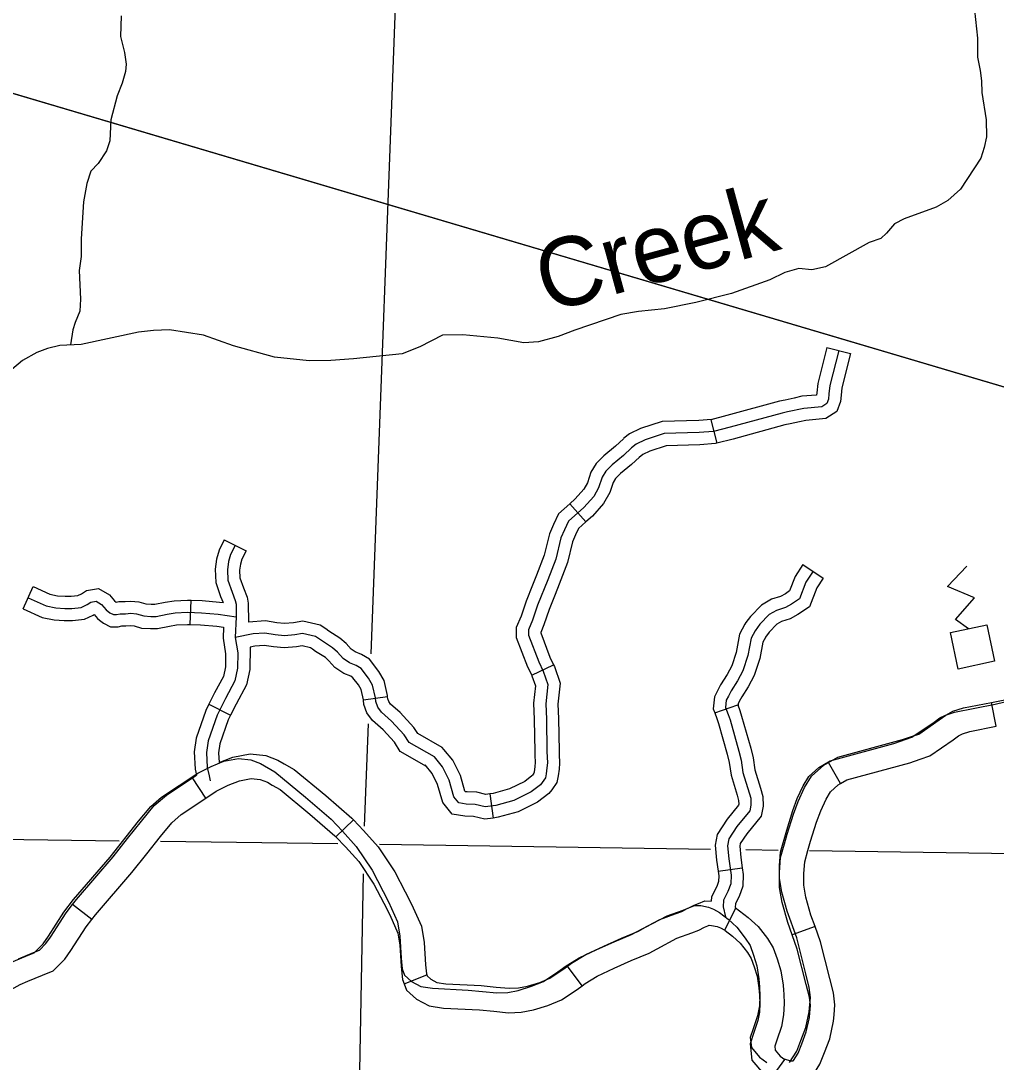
# Model space of a CAD drawing. Extents: x 0 to 3171, y 0 to 2059.
# Drawn here: x 1109.9 to 1210, y 749 to 855.9 of the extents above; entities that cross this region are included whole.
import ezdxf

# ---------------------------------------------------------------- set-up
doc = ezdxf.new("R2010")
doc.units = 0
for name, color, linetype in [('Default', 7, 'Continuous'), ('Level 35', 7, 'Continuous'), ('Level 45', 7, 'Continuous'), ('Level 5', 7, 'Continuous'), ('Level 57', 7, 'Continuous')]:
    doc.layers.add(name, color=color, linetype=linetype)

msp = doc.modelspace()

# ---------------------------------------------------------------- linework, layer by layer
at = {"layer": 'Default'}
for points in [[(641.57, 882.9), (992.89, 882.9), (1640.89, 690.88)], [(1029.42, 872.07), (1640.89, 690.88)]]:
    msp.add_lwpolyline(points, dxfattribs=at)
at = {"layer": 'Level 35'}
for points in [[(1207.74, 856.98), (1208.06, 854.1), (1208.04, 852.17), (1208.33, 850.79), (1208.46, 849.74), (1208.48, 848.52), (1208.95, 845.71), (1208.96, 843.97), (1208.74, 842.87), (1208.38, 841.78), (1206.31, 838.6), (1205, 837.44), (1203.81, 836.75), (1200.53, 835.58), (1199.52, 835.04), (1198.73, 834.1), (1198.14, 833.53), (1196.95, 833.15), (1192.45, 830.64), (1191.07, 830.33), (1189.72, 830.47), (1188.3, 830.07), (1186.73, 829.31), (1182.8, 827.9), (1179.15, 826.97), (1175.92, 826.32), (1173.28, 826.05), (1171.47, 825.75), (1166.72, 824.14), (1165.03, 823.47), (1163.01, 822.93), (1161.5, 822.83), (1158.85, 823.3), (1155.23, 823.67), (1153.17, 823.61), (1150.82, 822.44), (1149.02, 821.71), (1144.04, 821.18), (1141.7, 821.01), (1139.47, 820.98), (1135.93, 821.37), (1131.71, 822.52), (1128.63, 823.62), (1125.14, 824.16), (1123.49, 824.11), (1121.97, 823.92), (1116.08, 822.68), (1113.91, 822.56), (1112.63, 822.27), (1111.55, 821.85), (1110.05, 821.03), (1107.65, 819.02)], [(1120.17, 856.41), (1120.13, 854.26), (1120.53, 852.65), (1120.7, 851.43), (1120.62, 850.67), (1120.3, 849.48), (1119.79, 848.19), (1119.11, 845.74), (1119.03, 843.57), (1118.69, 842.55), (1117.82, 841.23), (1117.09, 840.44), (1116.65, 839.2), (1116.31, 837.32), (1116.07, 833.51), (1116.07, 831.71), (1115.86, 830.26), (1116.03, 827.33), (1115.94, 826.09), (1115.45, 824.91), (1115.24, 824.17), (1114.98, 822.62)]]:
    msp.add_lwpolyline(points, dxfattribs=at)
at = {"layer": 'Level 45'}
for p, q in [((1192.6, 822.36), (1195.03, 821.75)), ((1180.69, 814.95), (1181.32, 812.53)), ((1166.22, 806.32), (1167.88, 804.45)), ((1130.76, 802.61), (1133, 801.5)), ((1190.14, 800.08), (1192.23, 798.7)), ((1110.14, 795.54), (1111.17, 797.82)), ((1127.28, 793.92), (1127.38, 796.42)), ((1162.31, 788.72), (1164.56, 789.8)), ((1129.18, 785.74), (1131.42, 784.62)), ((1147.52, 786.49), (1145.04, 786.17)), ((1181.09, 784.85), (1183.45, 785.68)), ((1209.97, 783.48), (1209.48, 785.93)), ((1194.01, 777.61), (1192.78, 779.78)), ((1128.88, 776.11), (1127.49, 778.19)), ((1158.02, 776.55), (1158.35, 774.07)), ((1142.22, 772.14), (1144.02, 773.87)), ((1181.44, 768.61), (1183.91, 768.96)), ((1117.18, 763.67), (1115.2, 765.2)), ((1182.12, 762.56), (1183.26, 764.84)), ((1191.38, 762.92), (1189.03, 762.08)), ((1167.48, 756.86), (1165.98, 758.86)), ((1149.22, 757.05), (1151.54, 757.97)), ((1186.82, 747.27), (1188.28, 749.3))]:
    msp.add_line(p, q, dxfattribs=at)
for points in [[(1193.81, 822.06), (1192.9, 818.45), (1192.81, 817.59), (1192.76, 817.07), (1192.6, 816.6), (1192.08, 816.28), (1190.24, 816.11), (1188.57, 815.74), (1188, 815.63), (1182.66, 814.17), (1180.96, 813.73), (1179.51, 813.62), (1175.89, 813.53), (1173.94, 812.89), (1173.03, 812.44), (1172.55, 812.06), (1171.73, 811.28), (1170.56, 810.33), (1169.93, 809.68), (1169.53, 809.04), (1169.18, 807.97), (1168.67, 807.08), (1167.66, 805.93), (1166.1, 804.54), (1165.69, 803.66), (1165.31, 802.83), (1164.79, 800.65), (1163.97, 798.52), (1162.92, 795.9), (1162.4, 794.36), (1161.98, 793.37), (1161.98, 792.84), (1163.03, 790.1), (1163.49, 789.15), (1163.96, 787.76), (1163.75, 785.8), (1163.82, 784.23), (1163.87, 780.91), (1163.92, 779.74), (1163.87, 779.22), (1163.78, 778.59), (1163.71, 778.19), (1163.38, 777.7), (1163.2, 777.48), (1162.26, 776.76), (1160.48, 775.87), (1158.62, 775.37), (1157.55, 775.22), (1156.51, 775.47), (1155.58, 775.49), (1154.83, 775.62), (1154.33, 776.25), (1153.83, 777.97), (1153.16, 779.31), (1152.32, 780.34), (1149.72, 781.82), (1149.24, 782.6), (1147.93, 784.01), (1146.89, 784.92), (1146.53, 785.43), (1146.32, 786.01), (1146.27, 786.42)], [(1192.6, 822.36), (1191.67, 818.68), (1191.56, 817.71), (1191.54, 817.48), (1190.04, 817.35), (1189.25, 817.17)], [(1195.03, 821.75), (1194.14, 818.23), (1194.05, 817.46), (1193.99, 816.81), (1193.63, 815.78), (1192.5, 815.06), (1190.43, 814.88), (1189.8, 814.73)], [(1189.25, 817.17), (1188.32, 816.96), (1187.72, 816.85), (1182.34, 815.38), (1180.69, 814.95)], [(1180.75, 814.96), (1179.45, 814.87), (1175.68, 814.77), (1173.47, 814.05), (1172.36, 813.5), (1171.78, 813.04)], [(1189.8, 814.73), (1188.83, 814.51), (1188.28, 814.41), (1182.99, 812.96), (1181.32, 812.53)], [(1171.78, 813.04), (1171.73, 813), (1170.9, 812.22), (1169.72, 811.25), (1168.94, 810.45), (1168.39, 809.58), (1168.04, 808.48), (1167.65, 807.81), (1166.78, 806.81), (1166.22, 806.32)], [(1181.32, 812.53), (1181.16, 812.49), (1179.57, 812.37), (1176.11, 812.28), (1174.42, 811.73), (1173.71, 811.38), (1173.33, 811.08)], [(1173.37, 811.11), (1172.55, 810.34), (1171.41, 809.41), (1170.92, 808.9), (1170.68, 808.51), (1170.33, 807.46), (1169.69, 806.35), (1168.55, 805.05), (1167.88, 804.45)], [(1166.22, 806.32), (1165.07, 805.3), (1164.55, 804.18), (1164.13, 803.24), (1163.59, 801.03), (1162.8, 798.98), (1162.39, 797.95)], [(1167.88, 804.45), (1167.12, 803.78), (1166.82, 803.14), (1166.5, 802.42), (1165.98, 800.28), (1165.13, 798.07), (1164.71, 797.01)], [(1131.88, 802.05), (1131.4, 801.1), (1131.2, 800.39), (1131.08, 799.55), (1131.13, 798.48), (1131.56, 797.24), (1131.9, 796.4), (1131.97, 796.01), (1131.99, 794.71), (1131.9, 792.58), (1132.15, 791.01), (1132.13, 789.46), (1131.86, 788.16), (1130.88, 786.34), (1130.02, 784.62), (1129.1, 781.99), (1128.93, 780.81), (1129.01, 779.26), (1129.23, 778.39), (1129.33, 777.9)], [(1130.76, 802.61), (1130.23, 801.55), (1129.97, 800.65), (1129.83, 799.61), (1129.89, 798.24), (1130.39, 796.8), (1130.64, 796.18)], [(1133, 801.5), (1132.57, 800.64), (1132.42, 800.13), (1132.34, 799.49), (1132.37, 798.72), (1132.73, 797.68), (1133.11, 796.74), (1133.22, 796.13), (1133.25, 794.18)], [(1190.14, 800.08), (1189.33, 798.85), (1188.75, 797.37), (1188.34, 797.09), (1187.84, 796.82), (1186.92, 796.53), (1185.88, 795.93), (1184.77, 794.76), (1184.29, 794.12)], [(1191.19, 799.39), (1190.44, 798.27), (1189.78, 796.55), (1188.98, 796.02), (1188.34, 795.67), (1187.43, 795.38), (1186.67, 794.94), (1185.73, 793.95), (1185.23, 793.29), (1184.82, 792.53), (1184.5, 790.74), (1183.99, 789.19), (1183.43, 788.16), (1182.77, 787.13), (1182.49, 786.57), (1182.28, 786.15), (1182.21, 785.42), (1182.47, 784.7), (1182.66, 784.14), (1183.57, 780.93), (1183.8, 779.99), (1183.99, 778.75), (1184.79, 776.09), (1184.81, 775.38), (1184.69, 774.82), (1183.36, 773.21), (1182.52, 771.92), (1182.4, 771.22), (1182.52, 769.87), (1182.76, 768.19), (1182.73, 767.32), (1182.45, 766.53), (1181.99, 765.64), (1181.96, 764.96), (1182.19, 763.93)], [(1192.23, 798.7), (1191.56, 797.69), (1190.8, 795.73), (1189.63, 794.95), (1188.83, 794.51), (1187.93, 794.23), (1187.45, 793.95), (1186.68, 793.14), (1186.29, 792.62)], [(1111.17, 797.82), (1112.87, 797.05), (1113.65, 796.88), (1114.43, 796.83), (1115.05, 796.83), (1115.73, 796.91), (1116.11, 797.09), (1116.63, 797.41), (1117.86, 797.62), (1118.99, 796.96), (1119.5, 796.35), (1119.5, 796.35)], [(1162.39, 797.95), (1161.74, 796.33), (1161.23, 794.8), (1160.73, 793.63), (1160.73, 792.6), (1161.88, 789.6), (1162.31, 788.72)], [(1110.66, 796.68), (1112.48, 795.86), (1113.48, 795.64), (1114.39, 795.58), (1115.12, 795.58), (1116.08, 795.69), (1116.71, 795.99), (1117.08, 796.22), (1117.62, 796.31), (1118.17, 795.99), (1118.63, 795.45), (1119.04, 795.13), (1119.4, 794.95), (1119.72, 794.95), (1120.08, 795.04), (1120.63, 795.04), (1121.18, 795.08), (1121.77, 795.04), (1122.5, 794.81), (1123.22, 794.76), (1123.77, 794.76), (1124.91, 795), (1125.73, 795.13), (1126.99, 795.19), (1128.42, 795.13), (1130.15, 794.99), (1131.99, 794.71)], [(1119.5, 796.35), (1119.67, 796.22), (1119.93, 796.29), (1120.58, 796.29), (1121.17, 796.34), (1122.01, 796.27), (1122.72, 796.05), (1123.26, 796.01), (1123.64, 796.01), (1124.69, 796.23), (1125.61, 796.37), (1126.98, 796.44), (1127.38, 796.42)], [(1127.38, 796.42), (1128.49, 796.38), (1130.29, 796.23), (1130.64, 796.18)], [(1164.71, 797.01), (1164.09, 795.47), (1163.57, 793.91), (1163.23, 793.12), (1163.23, 793.07), (1164.18, 790.59), (1164.56, 789.8)], [(1110.14, 795.54), (1112.09, 794.66), (1113.31, 794.4), (1114.35, 794.33), (1115.19, 794.33), (1116.42, 794.47), (1117.32, 794.9), (1117.41, 794.96), (1117.75, 794.54), (1117.97, 794.38)], [(1117.97, 794.38), (1118.37, 794.07), (1119.1, 793.7), (1119.87, 793.7), (1120.24, 793.79), (1120.68, 793.79), (1121.18, 793.83), (1121.53, 793.8), (1122.27, 793.57), (1123.19, 793.51), (1123.9, 793.51), (1125.14, 793.77), (1125.85, 793.88), (1126.99, 793.93), (1127.28, 793.92)], [(1141.2, 793.47), (1140.62, 793.85), (1138.83, 794.28), (1137.86, 794.11), (1136.93, 794.03), (1136.16, 794.11), (1134.98, 794.31), (1133.25, 794.18)], [(1184.29, 794.12), (1184.17, 793.96), (1183.63, 792.94), (1183.29, 791.05), (1182.84, 789.69), (1182.35, 788.8), (1181.68, 787.75), (1181.37, 787.13), (1181.06, 786.5), (1180.94, 785.27), (1181.09, 784.85)], [(1127.28, 793.92), (1128.34, 793.88), (1130, 793.75), (1130.7, 793.64)], [(1130.7, 793.64), (1130.65, 792.51), (1130.9, 790.92), (1130.88, 789.6), (1130.67, 788.59), (1129.77, 786.91), (1129.18, 785.74)], [(1146.27, 786.42), (1145.99, 787.71), (1145.57, 788.42), (1144.82, 789.42), (1144.3, 789.73), (1143.62, 790), (1142.95, 790.45), (1142.38, 791.1), (1141.88, 791.53), (1140.83, 792.21), (1140.11, 792.69), (1138.79, 793.01), (1138.02, 792.87), (1136.93, 792.78), (1135.99, 792.87), (1134.92, 793.05), (1133.74, 792.96), (1131.9, 792.58)], [(1147.52, 786.49), (1147.5, 786.63), (1147.17, 788.17), (1146.62, 789.12), (1145.67, 790.36), (1144.86, 790.86), (1144.21, 791.11), (1143.79, 791.4), (1143.27, 791.99), (1142.63, 792.54), (1141.51, 793.26), (1141.2, 793.47)], [(1186.29, 792.62), (1186.29, 792.61), (1186.02, 792.11), (1185.72, 790.43), (1185.14, 788.69), (1184.51, 787.53), (1183.86, 786.52), (1183.61, 786.01), (1183.5, 785.8), (1183.48, 785.58), (1183.45, 785.68)], [(1133.41, 791.62), (1133.38, 789.32), (1133.04, 787.73), (1131.99, 785.76), (1131.42, 784.62)], [(1139.81, 791.39), (1139.6, 791.53), (1138.75, 791.73), (1138.18, 791.63), (1136.92, 791.52), (1135.83, 791.63), (1134.86, 791.79), (1133.91, 791.72), (1133.41, 791.62)], [(1145.04, 786.17), (1145.04, 786.21), (1144.81, 787.25), (1144.53, 787.73), (1143.97, 788.47), (1143.75, 788.61), (1143.03, 788.89), (1142.12, 789.51), (1141.5, 790.21), (1141.14, 790.53), (1140.14, 791.17), (1139.81, 791.39)], [(1164.56, 789.8), (1164.65, 789.62), (1165.24, 787.9), (1165, 785.76), (1165.07, 784.27), (1165.12, 780.94), (1165.14, 780.61)], [(1162.31, 788.72), (1162.33, 788.67), (1162.69, 787.62), (1162.49, 785.84), (1162.57, 784.19), (1162.62, 780.87), (1162.64, 780.51)], [(1209.48, 785.93), (1210.85, 786.2), (1212.89, 786.67), (1214.21, 787.13), (1214.95, 787.44), (1217.6, 788.54)], [(1203.59, 783.91), (1204.2, 784.34), (1204.76, 784.64), (1205.69, 784.94), (1209.85, 785.76), (1211.98, 786.25), (1213.41, 786.75)], [(1129.18, 785.74), (1128.86, 785.1), (1127.88, 782.28), (1127.68, 780.87), (1127.77, 779.07), (1127.92, 778.48)], [(1151.5, 779.37), (1148.83, 780.89), (1148.24, 781.84), (1147.06, 783.11), (1145.96, 784.07), (1145.4, 784.85), (1145.1, 785.73), (1145.04, 786.17)], [(1153.31, 781.11), (1153.14, 781.31), (1150.62, 782.75), (1150.23, 783.36), (1148.8, 784.91), (1147.83, 785.76), (1147.65, 786.01), (1147.55, 786.3), (1147.52, 786.49)], [(1183.45, 785.68), (1183.65, 785.11), (1183.85, 784.51), (1184.78, 781.25), (1185.03, 780.24), (1185.21, 779.03), (1185.77, 777.14)], [(1201.37, 782.47), (1202.02, 782.69), (1204.12, 784.15), (1204.79, 784.63), (1205.53, 785.02), (1206.63, 785.37), (1209.48, 785.93)], [(1131.42, 784.62), (1131.17, 784.13), (1130.32, 781.69), (1130.19, 780.75), (1130.24, 779.76)], [(1181.09, 784.85), (1181.29, 784.29), (1181.46, 783.77), (1182.36, 780.61), (1182.58, 779.75), (1182.77, 778.48), (1183.38, 776.43)], [(1188.77, 748.98), (1189.52, 750.15), (1189.94, 751.22), (1190.43, 752.56), (1190.79, 754.18), (1190.9, 755.65), (1190.78, 756.69), (1190.43, 758.07), (1189.5, 761.76), (1188.52, 764.5), (1187.98, 766.45), (1187.74, 767.85), (1187.72, 769.21), (1187.84, 770.57), (1188.48, 772.83), (1189.11, 774.84), (1189.55, 776.07), (1190.15, 777.38), (1190.75, 778.34), (1191.77, 779.27), (1192.93, 779.93), (1199.48, 781.72), (1201.33, 782.35), (1203.59, 783.91)], [(1202.17, 780.11), (1203.15, 780.44), (1205.56, 782.11), (1206.11, 782.5), (1206.5, 782.7), (1207.26, 782.95), (1209.97, 783.48)], [(1192.78, 779.78), (1193.71, 780.31), (1200.37, 782.13), (1201.37, 782.47)], [(1130.24, 779.76), (1131.63, 780.31), (1133.43, 780.65), (1135.04, 780.47), (1136.26, 780.01), (1136.92, 779.63)], [(1158.02, 776.55), (1157.62, 776.49), (1156.67, 776.71), (1155.7, 776.74), (1155.51, 776.77), (1155.46, 776.84), (1155, 778.42), (1154.22, 779.99), (1153.31, 781.11)], [(1162.64, 780.51), (1162.67, 779.77), (1162.63, 779.37), (1162.55, 778.79), (1162.53, 778.67), (1162.38, 778.45), (1162.33, 778.39), (1161.6, 777.83), (1160.03, 777.05), (1158.37, 776.59), (1158.02, 776.55)], [(1165.14, 780.61), (1165.17, 779.71), (1165.12, 779.07), (1165.01, 778.39), (1164.9, 777.72), (1164.38, 776.95), (1164.06, 776.57), (1162.92, 775.7), (1160.93, 774.7), (1158.86, 774.14), (1158.35, 774.07)], [(1108.03, 758.89), (1110.4, 759.89), (1111.26, 760.23), (1112.17, 761.16), (1112.72, 761.94), (1114.3, 764.39), (1115.31, 765.7), (1119.06, 770.06), (1121.98, 773.73), (1123.22, 775.25), (1124.34, 776.21), (1128.05, 778.68), (1129.42, 779.37), (1130.73, 779.89), (1132.23, 780.17), (1133.49, 780.03), (1134.47, 779.65), (1135.97, 778.81), (1139.11, 776.22), (1141.72, 773.94), (1142.89, 772.73), (1144.3, 771.13), (1145.93, 768.7), (1147.62, 765.47), (1148.55, 763.4), (1148.78, 761.95), (1148.92, 759.7), (1149.02, 758.58), (1149.27, 757.93), (1149.97, 757.29), (1150.93, 756.78), (1152.13, 756.59), (1155.8, 756.4), (1158.72, 756.12), (1159.85, 756.17), (1160.92, 756.38), (1162.3, 756.8), (1163.52, 757.29), (1164.99, 758.28), (1165.83, 758.91), (1167.19, 759.73), (1168.99, 760.57), (1170.77, 761.37), (1172.56, 762.13)], [(1136.92, 779.63), (1137.93, 779.06), (1141.17, 776.39), (1143.84, 774.07), (1144.02, 773.87)], [(1158.35, 774.07), (1157.49, 773.96), (1156.35, 774.22), (1155.45, 774.25), (1154.15, 774.47), (1153.19, 775.67), (1152.66, 777.51), (1152.1, 778.63), (1151.37, 779.53)], [(1188.25, 771.41), (1188.53, 772.41), (1189.17, 774.46), (1189.65, 775.76), (1190.3, 777.19), (1191.03, 778.36), (1192.28, 779.5), (1192.78, 779.78)], [(1194.01, 777.61), (1194.66, 777.98), (1201.1, 779.74), (1202.17, 780.11)], [(1120.85, 771.96), (1122.26, 773.73), (1123.58, 775.35), (1124.84, 776.43), (1127.92, 778.48)], [(1128.88, 776.11), (1129.93, 776.82), (1131.18, 777.45), (1132.33, 777.9), (1133.53, 778.12), (1134.45, 778.02), (1135.19, 777.74), (1135.69, 777.45)], [(1135.69, 777.45), (1136.51, 776.99), (1139.55, 774.48), (1142.11, 772.25), (1142.22, 772.14)], [(1185.77, 777.14), (1186.03, 776.29), (1186.06, 775.28), (1185.85, 774.26), (1184.37, 772.46), (1183.71, 771.45), (1183.66, 771.17), (1183.76, 770.01), (1183.91, 768.96)], [(1190.66, 770.73), (1190.93, 771.69), (1191.54, 773.65), (1191.96, 774.81), (1192.51, 776.01), (1192.97, 776.75), (1193.76, 777.47), (1194.01, 777.61)], [(1122.81, 770.41), (1124.21, 772.17), (1125.37, 773.59), (1126.35, 774.43), (1128.88, 776.11)], [(1183.38, 776.43), (1183.54, 775.88), (1183.55, 775.49), (1183.53, 775.38), (1182.35, 773.95), (1181.33, 772.38), (1181.14, 771.27), (1181.28, 769.73), (1181.44, 768.61)], [(1144.02, 773.87), (1145.06, 772.79), (1146.54, 771.12), (1148.26, 768.56), (1149.34, 766.48)], [(1115.2, 765.2), (1115.6, 765.71), (1119.35, 770.07), (1120.85, 771.96)], [(1142.22, 772.14), (1143.22, 771.1), (1144.56, 769.59), (1146.11, 767.28), (1147.13, 765.33)], [(1189.03, 762.08), (1188.58, 763.34), (1188.01, 765.39), (1187.75, 766.95), (1187.72, 768.47), (1187.85, 770.01), (1188.25, 771.41)], [(1191.38, 762.92), (1190.96, 764.1), (1190.45, 765.93), (1190.24, 767.18), (1190.22, 768.38), (1190.32, 769.56), (1190.66, 770.73)], [(1117.18, 763.67), (1117.54, 764.13), (1121.27, 768.48), (1122.81, 770.41)], [(1181.44, 768.61), (1181.51, 768.12), (1181.49, 767.55), (1181.3, 767.03), (1180.75, 765.97), (1180.73, 765.55)], [(1183.91, 768.96), (1184.01, 768.26), (1183.98, 767.09), (1183.6, 766.03), (1183.22, 765.3), (1183.2, 764.88)], [(1149.34, 766.48), (1149.99, 765.23), (1151.01, 762.98), (1151.28, 761.31), (1151.42, 759.01), (1151.5, 758.08), (1151.54, 757.97)], [(1147.13, 765.33), (1147.74, 764.14), (1148.59, 762.26), (1148.79, 761.03), (1148.93, 758.83), (1149.04, 757.51), (1149.22, 757.05)], [(1174, 762.86), (1176.2, 764.04), (1177.86, 764.62), (1178.44, 764.85), (1178.99, 765.13), (1179.43, 765.31), (1180.08, 765.58), (1180.73, 765.55)], [(1109.64, 759.61), (1111.18, 760.26), (1111.8, 760.51), (1112.46, 761.18), (1112.93, 761.85), (1114.53, 764.33), (1115.2, 765.2)], [(1172.56, 762.13), (1175.45, 763.67), (1177.04, 764.23), (1177.7, 764.49), (1178.26, 764.77), (1178.66, 764.94), (1179.05, 765.1), (1179.66, 765.08), (1180.46, 764.91), (1180.97, 764.7), (1181.58, 764.38), (1182.46, 763.7), (1183.37, 762.85), (1184.21, 761.75), (1184.71, 760.98), (1185.06, 760), (1185.41, 758.9), (1185.62, 757.56), (1185.67, 756.7), (1185.71, 755.81), (1185.67, 754.79), (1185.48, 753.76), (1185.03, 752.45), (1184.73, 751.56), (1184.85, 750.52), (1185.69, 749.51)], [(1183.2, 764.88), (1184.52, 763.87), (1185.55, 762.92), (1186.49, 761.69), (1187.09, 760.75), (1187.49, 759.62), (1187.88, 758.4), (1188.12, 756.91), (1188.14, 756.39)], [(1110.61, 757.31), (1112.12, 757.95), (1113.22, 758.38), (1114.39, 759.58), (1115.01, 760.46), (1116.58, 762.89), (1117.18, 763.67)], [(1165.98, 758.86), (1166.39, 759.16), (1167.85, 760.05), (1169.72, 760.92), (1171.52, 761.73), (1173.28, 762.47), (1174, 762.86)], [(1175.18, 760.66), (1177.21, 761.74), (1178.73, 762.28), (1179.46, 762.57), (1180.03, 762.85), (1180.38, 763), (1180.53, 763.06), (1180.76, 763.05), (1181.34, 762.93), (1181.69, 762.79), (1182.12, 762.56)], [(1182.12, 762.56), (1182.15, 762.54), (1182.91, 761.96), (1183.7, 761.23), (1184.44, 760.25), (1184.83, 759.65), (1185.12, 758.81), (1185.44, 757.83), (1185.63, 756.65), (1185.65, 756.26)], [(1190.84, 754.06), (1190.9, 754.84), (1190.8, 755.68), (1190.47, 756.98), (1189.55, 760.62), (1189.03, 762.08)], [(1193.33, 753.87), (1193.41, 754.89), (1193.27, 756.13), (1192.9, 757.59), (1191.95, 761.35), (1191.38, 762.92)], [(1167.48, 756.86), (1167.79, 757.09), (1169.03, 757.84), (1170.76, 758.65), (1172.52, 759.44), (1174.35, 760.21), (1175.18, 760.66)], [(1158.65, 756.72), (1160.01, 756.59), (1160.95, 756.63), (1161.87, 756.81), (1163.14, 757.2), (1164.18, 757.62), (1165.52, 758.51), (1165.98, 758.86)], [(1151.54, 757.97), (1151.58, 757.87), (1151.95, 757.54), (1152.59, 757.2), (1153.51, 757.05), (1157.14, 756.87), (1158.65, 756.72)], [(1101.75, 757.03), (1102.85, 757.1), (1103.94, 757.12), (1104.74, 756.98), (1105.2, 756.87), (1107.31, 756.25), (1108.54, 756.27), (1109.83, 756.98), (1110.61, 757.31)], [(1149.22, 757.05), (1149.47, 756.41), (1150.5, 755.48), (1151.78, 754.79), (1153.25, 754.56), (1156.96, 754.37), (1158.41, 754.23)], [(1158.41, 754.23), (1159.94, 754.09), (1161.24, 754.14), (1162.48, 754.38), (1163.97, 754.84), (1165.36, 755.4), (1166.97, 756.47), (1167.48, 756.86)], [(1185.65, 756.26), (1185.67, 755.85), (1185.71, 755.02), (1185.67, 754.15), (1185.52, 753.29), (1185.1, 752.07), (1184.71, 750.91), (1184.91, 749.22), (1186.08, 747.8), (1186.82, 747.27)], [(1188.14, 756.39), (1188.17, 755.98), (1188.22, 755.03), (1188.16, 753.87), (1187.94, 752.67), (1187.47, 751.27), (1187.26, 750.64), (1187.3, 750.25), (1187.8, 749.64), (1188.28, 749.3)], [(1186.82, 747.27), (1187.13, 747.05), (1188.55, 746.66), (1189.66, 746.66), (1190.88, 747.2), (1191.89, 748.79), (1192.36, 750), (1192.89, 751.42), (1193.28, 753.22), (1193.33, 753.87)], [(1188.22, 749.35), (1188.88, 749.16), (1189.13, 749.16), (1189.17, 749.18), (1189.65, 749.93), (1190.03, 750.88), (1190.48, 752.12), (1190.8, 753.58), (1190.84, 754.06)], [(1185.69, 749.51), (1186.42, 748.98)]]:
    msp.add_lwpolyline(points, dxfattribs=at)
at = {"layer": 'Level 5'}
for points in [[(1148.5, 862.8), (1145.79, 790.93)], [(1145.52, 783.74), (1145.12, 773.23)], [(1119.97, 771.71), (1083.32, 772.2), (1058.53, 772.6)], [(1142.43, 771.41), (1124.21, 771.66)], [(1180.65, 770.85), (1146.7, 771.35)], [(1187.6, 770.75), (1184.27, 770.8)], [(1232.86, 770.08), (1190.83, 770.7)], [(1145, 768.34), (1143.45, 683.7)]]:
    msp.add_lwpolyline(points, dxfattribs=at)
at = {"layer": 'Level 57'}
msp.add_lwpolyline([(1207.14, 793.5), (1205.78, 794.43), (1207.75, 796.68), (1204.99, 797.83), (1206.96, 799.93)], dxfattribs=at)
msp.add_lwpolyline([(1206.06, 789.36), (1205.27, 793.11), (1209.01, 793.9), (1209.8, 790.15)], close=True, dxfattribs=at)

# ---------------------------------------------------------------- texts
at = {"layer": 'Level 35'}
msp.add_text('Creek', height=7.04, rotation=15.1834, dxfattribs=at).set_placement((1163.84, 825.9))

doc.saveas('drawing.dxf')
